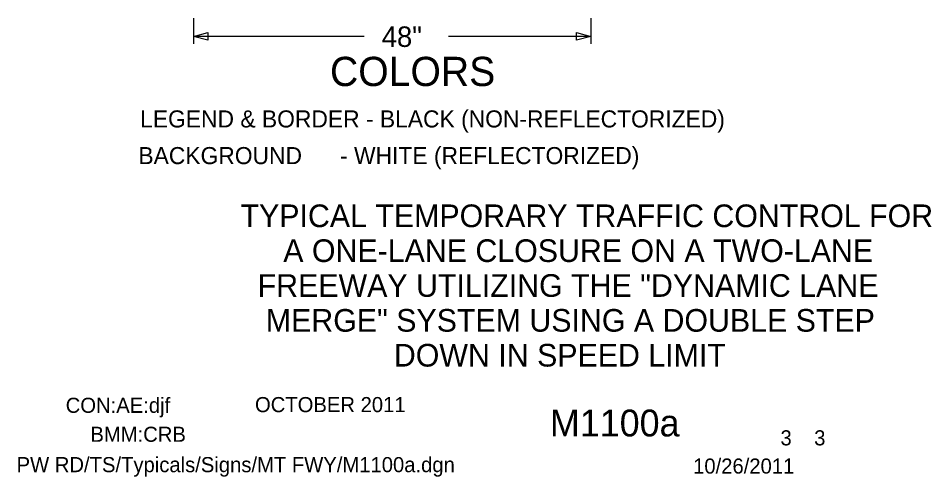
# Model space of a CAD drawing. Extents: x 15262 to 18126, y 1908 to 6555.
# Drawn here: x 17751.9 to 18126.4, y 2176.1 to 2364.2 of the extents above; entities that cross this region are included whole.
import ezdxf

# ---------------------------------------------------------------- set-up
doc = ezdxf.new("R2010")
doc.units = 0
doc.layers.add('BORDER_SIGNAL_WO', color=7, linetype='Continuous')
doc.layers.add('TYPICAL_TEXT_DIMEN_PR', color=7, linetype='Continuous')

msp = doc.modelspace()

# ---------------------------------------------------------------- linework, layer by layer
at = {"layer": 'TYPICAL_TEXT_DIMEN_PR'}
for p, q in [((17823.7, 2364.24), (17823.7, 2353.72)), ((17986.58, 2364.24), (17986.58, 2353.72)), ((17823.7, 2356.82), (17829.57, 2358.39)), ((17893.74, 2356.82), (17823.7, 2356.82)), ((17829.57, 2355.25), (17823.7, 2356.82)), ((17829.57, 2358.39), (17829.57, 2356.82)), ((17829.57, 2356.82), (17829.57, 2355.25)), ((17986.58, 2356.82), (17928.26, 2356.82)), ((17980.71, 2356.82), (17980.71, 2358.39)), ((17980.71, 2358.39), (17986.58, 2356.82)), ((17986.58, 2356.82), (17980.71, 2355.25)), ((17980.71, 2355.25), (17980.71, 2356.82))]:
    msp.add_line(p, q, dxfattribs=at)

# ---------------------------------------------------------------- texts
at = {"layer": 'BORDER_SIGNAL_WO'}
for s, height, p in [('TYPICAL TEMPORARY TRAFFIC CONTROL FOR', 9.3, (17842.98, 2278.54)), ('A ONE-LANE CLOSURE ON A TWO-LANE', 9.3, (17860.5, 2264.24)), ('FREEWAY UTILIZING THE "DYNAMIC LANE', 9.3, (17850, 2249.94)), ('MERGE" SYSTEM USING A DOUBLE STEP ', 9.3, (17853.35, 2235.64)), ('DOWN IN SPEED LIMIT', 9.3, (17905.85, 2221.34)), ('CON:AE:djf  ', 6.2, (17771.3, 2202.35)), ('    OCTOBER 2011    ', 6.2, (17839.7, 2202.63)), ('    M1100a   ', 11, (17953.48, 2192.67)), ('BMM:CRB   ', 6.2, (17781.43, 2190.46)), (' 3    3 ', 6.2, (18062.06, 2188.99)), ('PW RD/TS/Typicals/Signs/MT FWY/M1100a.dgn      ', 6.2, (17751.17, 2178)), ('10/26/2011    ', 6.2, (18028.54, 2177.42))]:
    msp.add_text(s, height=height, dxfattribs=at).set_placement(p)
at = {"layer": 'TYPICAL_TEXT_DIMEN_PR'}
for s, height, p in [('48"', 8.4, (17900.88, 2352.48)), ('COLORS', 12, (17879.66, 2336.42)), ('LEGEND & BORDER - BLACK (NON-REFLECTORIZED)', 7, (17801.82, 2319.44)), ('BACKGROUND      - WHITE (REFLECTORIZED)', 7, (17801.1, 2304.39))]:
    msp.add_text(s, height=height, dxfattribs=at).set_placement(p)

doc.saveas('drawing.dxf')
